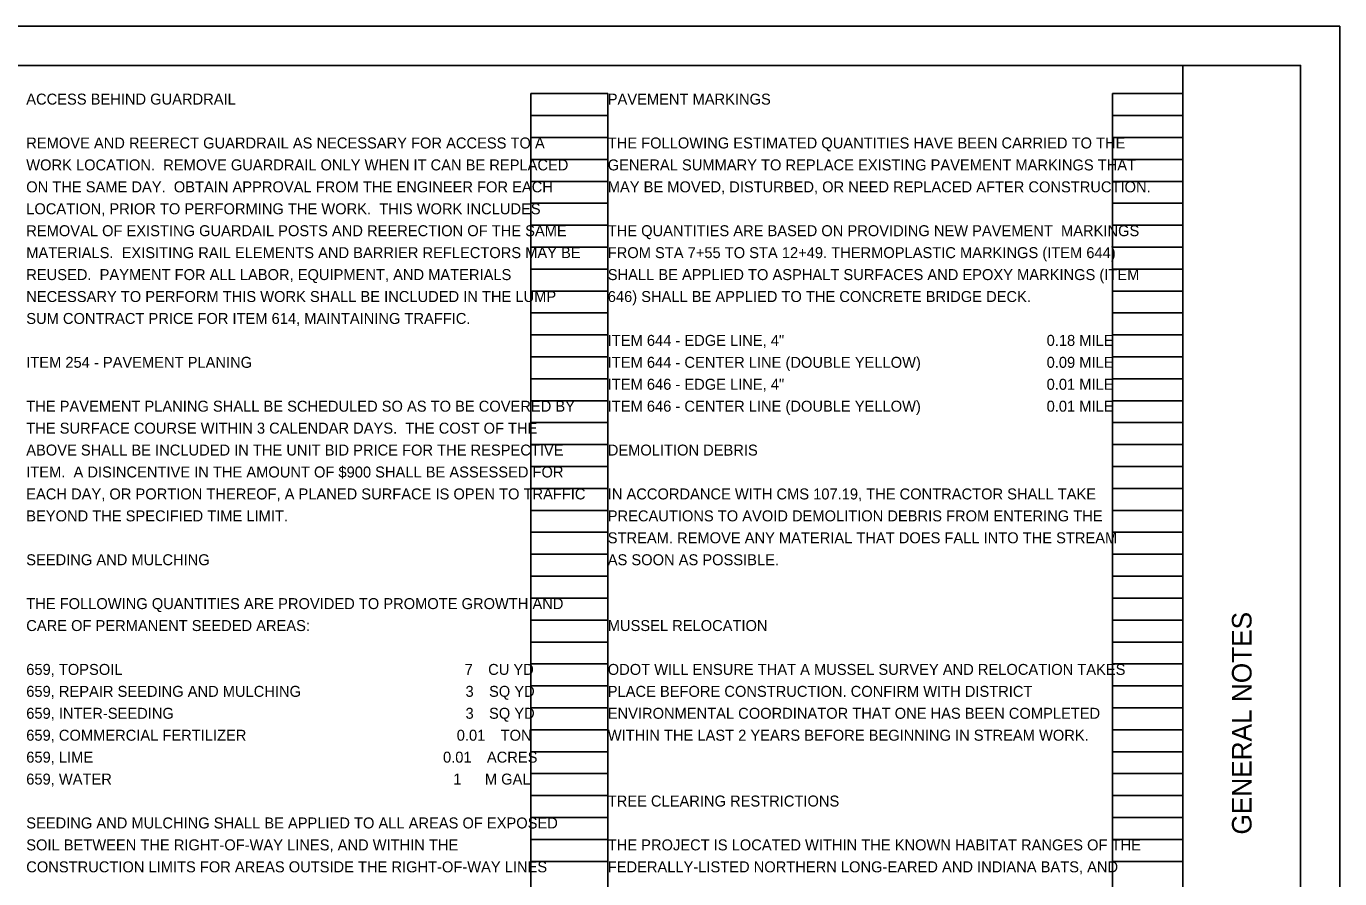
# Model space of a CAD drawing. Extents: x 0 to 34, y 0 to 22.
# Drawn here: x 17.24 to 34, y 11.12 to 22 of the extents above; entities that cross this region are included whole.
import ezdxf

# ---------------------------------------------------------------- set-up
doc = ezdxf.new("R2010")
doc.units = 0
for name, color, linetype in [('SH_Border', 7, 'Continuous'), ('SH_Cut_Line', 7, 'Continuous'), ('SH_Data', 7, 'Continuous'), ('SH_Text', 7, 'Continuous')]:
    doc.layers.add(name, color=color, linetype=linetype)

msp = doc.modelspace()

# ---------------------------------------------------------------- linework, layer by layer
at = {"layer": 'SH_Border'}
msp.add_line((32, 0.5), (32, 21.5), dxfattribs=at)
msp.add_lwpolyline([(1.5, 21.5), (33.5, 21.5), (33.5, 0.5), (1.5, 0.5)], close=True, dxfattribs=at)
at = {"layer": 'SH_Cut_Line'}
msp.add_lwpolyline([(0, 0), (34, 0), (34, 22), (0, 22)], close=True, dxfattribs=at)
at = {"layer": 'SH_Data'}
for p, q in [((23.68, 0.98), (23.68, 21.14)), ((23.68, 21.14), (24.66, 21.14)), ((24.66, 0.98), (24.66, 21.14)), ((31.1, 0.98), (31.1, 21.14)), ((31.1, 21.14), (32, 21.14)), ((32, 0.98), (32, 21.14)), ((23.68, 20.86), (24.66, 20.86)), ((31.1, 20.86), (32, 20.86)), ((23.68, 20.58), (24.66, 20.58)), ((31.1, 20.58), (32, 20.58)), ((23.68, 20.3), (24.66, 20.3)), ((31.1, 20.3), (32, 20.3)), ((23.68, 20.02), (24.66, 20.02)), ((31.1, 20.02), (32, 20.02)), ((23.68, 19.74), (24.66, 19.74)), ((31.1, 19.74), (32, 19.74)), ((23.68, 19.46), (24.66, 19.46)), ((31.1, 19.46), (32, 19.46)), ((23.68, 19.18), (24.66, 19.18)), ((31.1, 19.18), (32, 19.18)), ((23.68, 18.9), (24.66, 18.9)), ((31.1, 18.9), (32, 18.9)), ((23.68, 18.62), (24.66, 18.62)), ((31.1, 18.62), (32, 18.62)), ((23.68, 18.34), (24.66, 18.34)), ((31.1, 18.34), (32, 18.34)), ((23.68, 18.06), (24.66, 18.06)), ((31.1, 18.06), (32, 18.06)), ((23.68, 17.78), (24.66, 17.78)), ((31.1, 17.78), (32, 17.78)), ((23.68, 17.5), (24.66, 17.5)), ((31.1, 17.5), (32, 17.5)), ((23.68, 17.22), (24.66, 17.22)), ((31.1, 17.22), (32, 17.22)), ((23.68, 16.94), (24.66, 16.94)), ((31.1, 16.94), (32, 16.94)), ((23.68, 16.66), (24.66, 16.66)), ((31.1, 16.66), (32, 16.66)), ((23.68, 16.38), (24.66, 16.38)), ((31.1, 16.38), (32, 16.38)), ((23.68, 16.1), (24.66, 16.1)), ((31.1, 16.1), (32, 16.1)), ((23.68, 15.82), (24.66, 15.82)), ((31.1, 15.82), (32, 15.82)), ((23.68, 15.54), (24.66, 15.54)), ((31.1, 15.54), (32, 15.54)), ((23.68, 15.26), (24.66, 15.26)), ((31.1, 15.26), (32, 15.26)), ((23.68, 14.98), (24.66, 14.98)), ((31.1, 14.98), (32, 14.98)), ((23.68, 14.7), (24.66, 14.7)), ((31.1, 14.7), (32, 14.7)), ((23.68, 14.42), (24.66, 14.42)), ((31.1, 14.42), (32, 14.42)), ((23.68, 14.14), (24.66, 14.14)), ((31.1, 14.14), (32, 14.14)), ((23.68, 13.86), (24.66, 13.86)), ((31.1, 13.86), (32, 13.86)), ((23.68, 13.58), (24.66, 13.58)), ((31.1, 13.58), (32, 13.58)), ((23.68, 13.3), (24.66, 13.3)), ((31.1, 13.3), (32, 13.3)), ((23.68, 13.02), (24.66, 13.02)), ((31.1, 13.02), (32, 13.02)), ((23.68, 12.74), (24.66, 12.74)), ((31.1, 12.74), (32, 12.74)), ((23.68, 12.46), (24.66, 12.46)), ((31.1, 12.46), (32, 12.46)), ((23.68, 12.18), (24.66, 12.18)), ((31.1, 12.18), (32, 12.18)), ((23.68, 11.9), (24.66, 11.9)), ((31.1, 11.9), (32, 11.9)), ((23.68, 11.62), (24.66, 11.62)), ((31.1, 11.62), (32, 11.62)), ((23.68, 11.34), (24.66, 11.34)), ((31.1, 11.34), (32, 11.34))]:
    msp.add_line(p, q, dxfattribs=at)

# ---------------------------------------------------------------- texts
msp.add_text('GENERAL NOTES', height=0.25, rotation=90, dxfattribs=at).set_placement((32.875, 11.682))
at = {"layer": 'SH_Text'}
for s, p in [('ACCESS BEHIND GUARDRAIL', (17.24, 21)), ('PAVEMENT MARKINGS', (24.66, 21)), ('REMOVE AND REERECT GUARDRAIL AS NECESSARY FOR ACCESS TO A ', (17.24, 20.44)), ('THE FOLLOWING ESTIMATED QUANTITIES HAVE BEEN CARRIED TO THE', (24.66, 20.44)), ('WORK LOCATION.  REMOVE GUARDRAIL ONLY WHEN IT CAN BE REPLACED ', (17.24, 20.16)), ('GENERAL SUMMARY TO REPLACE EXISTING PAVEMENT MARKINGS THAT', (24.66, 20.16)), ('ON THE SAME DAY.  OBTAIN APPROVAL FROM THE ENGINEER FOR EACH ', (17.24, 19.88)), ('MAY BE MOVED, DISTURBED, OR NEED REPLACED AFTER CONSTRUCTION.', (24.66, 19.88)), ('LOCATION, PRIOR TO PERFORMING THE WORK.  THIS WORK INCLUDES ', (17.24, 19.6)), ('REMOVAL OF EXISTING GUARDAIL POSTS AND REERECTION OF THE SAME ', (17.24, 19.32)), ('THE QUANTITIES ARE BASED ON PROVIDING NEW PAVEMENT  MARKINGS', (24.66, 19.32)), ('MATERIALS.  EXISITING RAIL ELEMENTS AND BARRIER REFLECTORS MAY BE ', (17.24, 19.04)), ('FROM STA 7+55 TO STA 12+49. THERMOPLASTIC MARKINGS (ITEM 644)', (24.66, 19.04)), ('REUSED.  PAYMENT FOR ALL LABOR, EQUIPMENT, AND MATERIALS ', (17.24, 18.76)), ('SHALL BE APPLIED TO ASPHALT SURFACES AND EPOXY MARKINGS (ITEM ', (24.66, 18.76)), ('NECESSARY TO PERFORM THIS WORK SHALL BE INCLUDED IN THE LUMP ', (17.24, 18.48)), ('646) SHALL BE APPLIED TO THE CONCRETE BRIDGE DECK.', (24.66, 18.48)), ('SUM CONTRACT PRICE FOR ITEM 614, MAINTAINING TRAFFIC.', (17.24, 18.2)), ('ITEM 644 - EDGE LINE, 4" ', (24.66, 17.92)), ('0.18 MILE', (30.26, 17.92)), ('ITEM 254 - PAVEMENT PLANING', (17.24, 17.64)), ('ITEM 644 - CENTER LINE (DOUBLE YELLOW)', (24.66, 17.64)), ('0.09 MILE', (30.26, 17.64)), ('ITEM 646 - EDGE LINE, 4" ', (24.66, 17.36)), ('0.01 MILE', (30.26, 17.36)), ('THE PAVEMENT PLANING SHALL BE SCHEDULED SO AS TO BE COVERED BY ', (17.24, 17.08)), ('ITEM 646 - CENTER LINE (DOUBLE YELLOW)', (24.66, 17.08)), ('0.01 MILE', (30.26, 17.08)), ('THE SURFACE COURSE WITHIN 3 CALENDAR DAYS.  THE COST OF THE ', (17.24, 16.8)), ('ABOVE SHALL BE INCLUDED IN THE UNIT BID PRICE FOR THE RESPECTIVE ', (17.24, 16.52)), ('DEMOLITION DEBRIS', (24.66, 16.52)), ('ITEM.  A DISINCENTIVE IN THE AMOUNT OF $900 SHALL BE ASSESSED FOR ', (17.24, 16.24)), ('EACH DAY, OR PORTION THEREOF, A PLANED SURFACE IS OPEN TO TRAFFIC ', (17.24, 15.96)), ('IN ACCORDANCE WITH CMS 107.19, THE CONTRACTOR SHALL TAKE', (24.66, 15.96)), ('BEYOND THE SPECIFIED TIME LIMIT.', (17.24, 15.68)), ('PRECAUTIONS TO AVOID DEMOLITION DEBRIS FROM ENTERING THE', (24.66, 15.68)), ('STREAM. REMOVE ANY MATERIAL THAT DOES FALL INTO THE STREAM', (24.66, 15.4)), ('SEEDING AND MULCHING', (17.24, 15.12)), ('AS SOON AS POSSIBLE.', (24.66, 15.12)), ('THE FOLLOWING QUANTITIES ARE PROVIDED TO PROMOTE GROWTH AND ', (17.24, 14.56)), ('CARE OF PERMANENT SEEDED AREAS:', (17.24, 14.28)), ('MUSSEL RELOCATION', (24.66, 14.28)), ('659, TOPSOIL                                               ', (17.24, 13.72)), ('     7', (22.574, 13.72)), ('CU YD', (23.134, 13.72)), ('ODOT WILL ENSURE THAT A MUSSEL SURVEY AND RELOCATION TAKES ', (24.66, 13.72)), ('659, REPAIR SEEDING AND MULCHING   ', (17.24, 13.44)), ('     3', (22.585, 13.44)), ('SQ YD', (23.145, 13.44)), ('PLACE BEFORE CONSTRUCTION. CONFIRM WITH DISTRICT ', (24.66, 13.44)), ('659, INTER-SEEDING   ', (17.24, 13.16)), ('     3', (22.585, 13.16)), ('SQ YD', (23.145, 13.16)), ('ENVIRONMENTAL COORDINATOR THAT ONE HAS BEEN COMPLETED ', (24.66, 13.16)), ('659, COMMERCIAL FERTILIZER             ', (17.24, 12.88)), ('0.01', (22.733, 12.88)), ('TON', (23.293, 12.88)), ('WITHIN THE LAST 2 YEARS BEFORE BEGINNING IN STREAM WORK.', (24.66, 12.88)), ('659, LIME                                                 ', (17.24, 12.6)), ('0.01', (22.558, 12.6)), ('ACRES', (23.118, 12.6)), ('659, WATER                                            ', (17.24, 12.32)), ('   1', (22.532, 12.32)), ('M GAL', (23.092, 12.32)), ('TREE CLEARING RESTRICTIONS', (24.66, 12.04)), ('SEEDING AND MULCHING SHALL BE APPLIED TO ALL AREAS OF EXPOSED ', (17.24, 11.76)), ('SOIL BETWEEN THE RIGHT-OF-WAY LINES, AND WITHIN THE ', (17.24, 11.48)), ('THE PROJECT IS LOCATED WITHIN THE KNOWN HABITAT RANGES OF THE ', (24.66, 11.48)), ('CONSTRUCTION LIMITS FOR AREAS OUTSIDE THE RIGHT-OF-WAY LINES ', (17.24, 11.2)), ('FEDERALLY-LISTED NORTHERN LONG-EARED AND INDIANA BATS, AND ', (24.66, 11.2))]:
    msp.add_text(s, height=0.14, dxfattribs=at).set_placement(p)

doc.saveas('drawing.dxf')
